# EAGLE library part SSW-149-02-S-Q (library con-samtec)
THROUGH-HOLE .025" SQ POST SOCKET Source: Samtec SSW.pdf
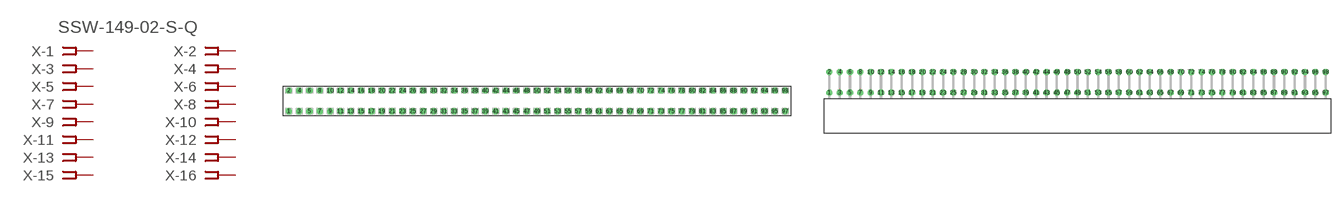
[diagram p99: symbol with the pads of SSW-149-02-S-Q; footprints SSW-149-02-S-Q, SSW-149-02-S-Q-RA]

Designator prefix X; gates -1=FPINV -2=FPIN -3=FPIN -4=FPIN -5=FPIN -6=FPIN -7=FPIN -8=FPIN -9=FPIN -10=FPIN -11=FPIN -12=FPIN -13=FPIN -14=FPIN -15=FPIN -16=FPIN -17=FPIN -18=FPIN -19=FPIN -20=FPIN -21=FPIN -22=FPIN -23=FPIN -24=FPIN -25=FPIN -26=FPIN -27=FPIN -28=FPIN -29=FPIN -30=FPIN -31=FPIN -32=FPIN -33=FPIN -34=FPIN -35=FPIN -36=FPIN -37=FPIN -38=FPIN -39=FPIN -40=FPIN -41=FPIN -42=FPIN -43=FPIN -44=FPIN -45=FPIN -46=FPIN -47=FPIN -48=FPIN -49=FPIN -50=FPIN -51=FPIN -52=FPIN -53=FPIN -54=FPIN -55=FPIN -56=FPIN -57=FPIN -58=FPIN -59=FPIN -60=FPIN -61=FPIN -62=FPIN -63=FPIN -64=FPIN -65=FPIN -66=FPIN -67=FPIN -68=FPIN -69=FPIN -70=FPIN -71=FPIN -72=FPIN -73=FPIN -74=FPIN -75=FPIN -76=FPIN -77=FPIN -78=FPIN -79=FPIN -80=FPIN -81=FPIN -82=FPIN -83=FPIN -84=FPIN -85=FPIN -86=FPIN -87=FPIN -88=FPIN -89=FPIN -90=FPIN -91=FPIN -92=FPIN -93=FPIN -94=FPIN -95=FPIN -96=FPIN -97=FPIN -98=FPIN

## SSW-149-02-S-Q (OC_FARNELL: unknown; OC_NEWARK: unknown)  [SSW-149-02-S-Q]
1  -1:1  pas
2  -2:1  pas
3  -3:1  pas
4  -4:1  pas
5  -5:1  pas
6  -6:1  pas
7  -7:1  pas
8  -8:1  pas
9  -9:1  pas
10  -10:1  pas
11  -11:1  pas
12  -12:1  pas
13  -13:1  pas
14  -14:1  pas
15  -15:1  pas
16  -16:1  pas
17  -17:1  pas
18  -18:1  pas
19  -19:1  pas
20  -20:1  pas
21  -21:1  pas
22  -22:1  pas
23  -23:1  pas
24  -24:1  pas
25  -25:1  pas
26  -26:1  pas
27  -27:1  pas
28  -28:1  pas
29  -29:1  pas
30  -30:1  pas
31  -31:1  pas
32  -32:1  pas
33  -33:1  pas
34  -34:1  pas
35  -35:1  pas
36  -36:1  pas
37  -37:1  pas
38  -38:1  pas
39  -39:1  pas
40  -40:1  pas
41  -41:1  pas
42  -42:1  pas
43  -43:1  pas
44  -44:1  pas
45  -45:1  pas
46  -46:1  pas
47  -47:1  pas
48  -48:1  pas
49  -49:1  pas
50  -50:1  pas
51  -51:1  pas
52  -52:1  pas
53  -53:1  pas
54  -54:1  pas
55  -55:1  pas
56  -56:1  pas
57  -57:1  pas
58  -58:1  pas
59  -59:1  pas
60  -60:1  pas
61  -61:1  pas
62  -62:1  pas
63  -63:1  pas
64  -64:1  pas
65  -65:1  pas
66  -66:1  pas
67  -67:1  pas
68  -68:1  pas
69  -69:1  pas
70  -70:1  pas
71  -71:1  pas
72  -72:1  pas
73  -73:1  pas
74  -74:1  pas
75  -75:1  pas
76  -76:1  pas
77  -77:1  pas
78  -78:1  pas
79  -79:1  pas
80  -80:1  pas
81  -81:1  pas
82  -82:1  pas
83  -83:1  pas
84  -84:1  pas
85  -85:1  pas
86  -86:1  pas
87  -87:1  pas
88  -88:1  pas
89  -89:1  pas
90  -90:1  pas
91  -91:1  pas
92  -92:1  pas
93  -93:1  pas
94  -94:1  pas
95  -95:1  pas
96  -96:1  pas
97  -97:1  pas
98  -98:1  pas

## SSW-149-02-S-QRA (OC_FARNELL: unknown; OC_NEWARK: unknown)  [SSW-149-02-S-Q-RA]
Pads as for SSW-149-02-S-Q

## Footprint SSW-149-02-S-Q (pad centres in mm)
THROUGH-HOLE .025" SQ POST SOCKET Source: Samtec SSW.pdf
drill 1 pad 1.5 octagon: 1 -60.96,-2.54; 2 -60.96,2.54; 3 -58.42,-2.54; 4 -58.42,2.54; 5 -55.88,-2.54; 6 -55.88,2.54; 7 -53.34,-2.54; 8 -53.34,2.54; 9 -50.8,-2.54; 10 -50.8,2.54; 11 -48.26,-2.54; 12 -48.26,2.54; 13 -45.72,-2.54; 14 -45.72,2.54; 15 -43.18,-2.54; 16 -43.18,2.54; 17 -40.64,-2.54; 18 -40.64,2.54; 19 -38.1,-2.54; 20 -38.1,2.54; 21 -35.56,-2.54; 22 -35.56,2.54; 23 -33.02,-2.54; 24 -33.02,2.54; 25 -30.48,-2.54; 26 -30.48,2.54; 27 -27.94,-2.54; 28 -27.94,2.54; 29 -25.4,-2.54; 30 -25.4,2.54; 31 -22.86,-2.54; 32 -22.86,2.54; 33 -20.32,-2.54; 34 -20.32,2.54; 35 -17.78,-2.54; 36 -17.78,2.54; 37 -15.24,-2.54; 38 -15.24,2.54; 39 -12.7,-2.54; 40 -12.7,2.54; 41 -10.16,-2.54; 42 -10.16,2.54; 43 -7.62,-2.54; 44 -7.62,2.54; 45 -5.08,-2.54; 46 -5.08,2.54; 47 -2.54,-2.54; 48 -2.54,2.54; 49 0,-2.54; 50 0,2.54; 51 2.54,-2.54; 52 2.54,2.54; 53 5.08,-2.54; 54 5.08,2.54; 55 7.62,-2.54; 56 7.62,2.54; 57 10.16,-2.54; 58 10.16,2.54; 59 12.7,-2.54; 60 12.7,2.54; 61 15.24,-2.54; 62 15.24,2.54; 63 17.78,-2.54; 64 17.78,2.54; 65 20.32,-2.54; 66 20.32,2.54; 67 22.86,-2.54; 68 22.86,2.54; 69 25.4,-2.54; 70 25.4,2.54; 71 27.94,-2.54; 72 27.94,2.54; 73 30.48,-2.54; 74 30.48,2.54; 75 33.02,-2.54; 76 33.02,2.54; 77 35.56,-2.54; 78 35.56,2.54; 79 38.1,-2.54; 80 38.1,2.54; 81 40.64,-2.54; 82 40.64,2.54; 83 43.18,-2.54; 84 43.18,2.54; 85 45.72,-2.54; 86 45.72,2.54; 87 48.26,-2.54; 88 48.26,2.54; 89 50.8,-2.54; 90 50.8,2.54; 91 53.34,-2.54; 92 53.34,2.54; 93 55.88,-2.54; 94 55.88,2.54; 95 58.42,-2.54; 96 58.42,2.54; 97 60.96,-2.54; 98 60.96,2.54

## Footprint SSW-149-02-S-Q-RA (pad centres in mm)
THROUGH-HOLE .025" SQ POST SOCKET Source: Samtec SSW.pdf
drill 1 pad 1.5 octagon: 1 -60.96,1.524; 2 -60.96,6.604; 3 -58.42,1.524; 4 -58.42,6.604; 5 -55.88,1.524; 6 -55.88,6.604; 7 -53.34,1.524; 8 -53.34,6.604; 9 -50.8,1.524; 10 -50.8,6.604; 11 -48.26,1.524; 12 -48.26,6.604; 13 -45.72,1.524; 14 -45.72,6.604; 15 -43.18,1.524; 16 -43.18,6.604; 17 -40.64,1.524; 18 -40.64,6.604; 19 -38.1,1.524; 20 -38.1,6.604; 21 -35.56,1.524; 22 -35.56,6.604; 23 -33.02,1.524; 24 -33.02,6.604; 25 -30.48,1.524; 26 -30.48,6.604; 27 -27.94,1.524; 28 -27.94,6.604; 29 -25.4,1.524; 30 -25.4,6.604; 31 -22.86,1.524; 32 -22.86,6.604; 33 -20.32,1.524; 34 -20.32,6.604; 35 -17.78,1.524; 36 -17.78,6.604; 37 -15.24,1.524; 38 -15.24,6.604; 39 -12.7,1.524; 40 -12.7,6.604; 41 -10.16,1.524; 42 -10.16,6.604; 43 -7.62,1.524; 44 -7.62,6.604; 45 -5.08,1.524; 46 -5.08,6.604; 47 -2.54,1.524; 48 -2.54,6.604; 49 0,1.524; 50 0,6.604; 51 2.54,1.524; 52 2.54,6.604; 53 5.08,1.524; 54 5.08,6.604; 55 7.62,1.524; 56 7.62,6.604; 57 10.16,1.524; 58 10.16,6.604; 59 12.7,1.524; 60 12.7,6.604; 61 15.24,1.524; 62 15.24,6.604; 63 17.78,1.524; 64 17.78,6.604; 65 20.32,1.524; 66 20.32,6.604; 67 22.86,1.524; 68 22.86,6.604; 69 25.4,1.524; 70 25.4,6.604; 71 27.94,1.524; 72 27.94,6.604; 73 30.48,1.524; 74 30.48,6.604; 75 33.02,1.524; 76 33.02,6.604; 77 35.56,1.524; 78 35.56,6.604; 79 38.1,1.524; 80 38.1,6.604; 81 40.64,1.524; 82 40.64,6.604; 83 43.18,1.524; 84 43.18,6.604; 85 45.72,1.524; 86 45.72,6.604; 87 48.26,1.524; 88 48.26,6.604; 89 50.8,1.524; 90 50.8,6.604; 91 53.34,1.524; 92 53.34,6.604; 93 55.88,1.524; 94 55.88,6.604; 95 58.42,1.524; 96 58.42,6.604; 97 60.96,1.524; 98 60.96,6.604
